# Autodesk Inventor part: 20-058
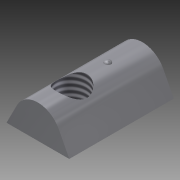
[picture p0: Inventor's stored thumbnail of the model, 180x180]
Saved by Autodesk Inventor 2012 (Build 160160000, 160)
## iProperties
Created: 2004-10
Part Number: 20-058
Material: Steel, High Strength Low Alloy
Document SubType Name: Modeling
Designer: Autodesk, Inc.
Manufacturer: Standard
Standards Organization: Custom
Description: NUT, T SLOT, STANDARD, 40 SERIES, M8
Catalog Web Link: http://www.parker.com/ead/cm1.asp?cmid=809
Vendor: PARKER IPS
Mass: 10.738 g
Surface Area: 10.2004 cm^2
Volume: 1.36964 cm^3
Density: 7.84 g/cm^3
CAGE: 1LJX3
Dept. ID: Product Design
Description #2: ---
Finish #1: ---
Finish #2: ---
Material ID: ---
Project Number: ---
Author: Autodesk, Inc.
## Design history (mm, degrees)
sketch "Sketch2"
  geometry: L1 (6.9, -11.5)-(-6.9, -11.5); L2 (-6.9, -11.5)-(-6.9, 11.5); L3 (-6.9, 11.5)-(6.9, 11.5); L4 (6.9, 11.5)-(6.9, -11.5); 5 further points
  constraints: 8 end point, 3 midpoint, 2 parallel, 2 vertical alignment, 1 horizontal, 1 horizontal alignment, 1 perpendicular
  dimensions: "CenterHole" = 7.5 distance from line of point (0, 4) L3; "Length" = 23 distance of L3.end L1.start; "Width" = 13.8 distance of L2.end L3.end
extrude "NutBase" new body sketch "Sketch2" taper "d4" = 0 deg; distance "Depth" = 7.3
hole "Hole1" sketch "Sketch2" diameter "HoleDia" = 6.647; stored, may be unused: countersink angle "d9" = 90 deg, drill point angle "d11" = 118 deg; dims "d6" = 6, "d7" = 4, "d8" = 2, "d10" = 8
node "MidPlane"
workplane "Work Plane4"
sketch "Sketch3"
  geometry: L1 (0, -7.3)-(13.8, -7.3) reference; L2 (13.8, 0)-(0, 0) reference; L3 (0, 0)-(2.3, -4.488); L4 (11.5, -4.488)-(13.8, 0); L5 (6.9, -2.131)-(6.9, 0); A1 r 5.169 centre (6.9, -2.131) between (2.3, -4.488) and (11.5, -4.488)
  constraints: 6 end point, 3 tangent, 2 point on circle, 1 centre point, 1 midpoint, 1 vertical
  dimensions: "d12" = 9.2 distance of L4.start L3.end (= 0.666667 x Width)
extrude "Standard TSlot" sketch "Sketch3" stored distance "d13" = 10; taper "d14" = 0 deg
sketch "Sketch5"
  geometry: L1 (0, -7.3)-(13.8, -7.3) reference; L2 (13.8, 0)-(0, 0) reference; L3 (0, 0)-(0, -7.3) reference; L4 (6.9, 0)-(6.9, -7.3); L5 (0, -0.8)-(2.95, -0.8); L6 (2.95, -0.8)-(2.95, 0); L7 (2.95, 0)-(0, 0); L8 (0, 0)-(0, -0.8); L9 (13.8, -0.8)-(10.85, -0.8); L10 (10.85, -0.8)-(10.85, 0); L11 (10.85, 0)-(13.8, 0); L12 (13.8, 0)-(13.8, -0.8); 1 further point
  constraints: 18 end point, 5 symmetric about line, 2 midpoint, 2 parallel, 2 point on line, 1 horizontal, 1 perpendicular
  dimensions: "Slot_Width" = 7.9 diameter of L6 L4; "d18" = 0.8 distance between parallel lines of L2 L5
extrude "Self-Align TSlot" cut sketch "Sketch5" stored distance "d19" = 10; taper "d20" = 0 deg
sketch "Sketch6"
  geometry: L1 (0, -7.3)-(13.8, -7.3) reference; L2 (13.8, 0)-(13.8, -7.3) reference; L3 (13.8, 0)-(0, 0) reference; L4 (0, 0)-(0, -7.3) reference; L5 (6.9, 0)-(6.9, -7.3); L6 (0, 0)-(2.95, 0); L7 (2.95, 0)-(2.95, -3.5); L8 (2.95, -3.5)-(0, -3.5); L9 (0, -3.5)-(0, 0); L10 (13.8, 0)-(10.85, 0); L11 (10.85, 0)-(10.85, -3.5); L12 (10.85, -3.5)-(13.8, -3.5); L13 (13.8, -3.5)-(13.8, 0); A1 r 2.5 centre (2.5, -4.8) between (0, -4.8) and (2.5, -7.3); A2 r 2.5 centre (11.3, -4.8) between (11.3, -7.3) and (13.8, -4.8)
  constraints: 18 end point, 4 point on circle, 4 point on line, 4 tangent, 3 symmetric about line, 2 centre point, 2 midpoint, 2 parallel, 1 horizontal, 1 perpendicular, 1 other
  dimensions: "HD_Slot_Depth" = 3.5 distance of L8.end L3.end; "HD_Slot_Width" = 7.9 diameter of L7 L5 (= Slot_Width); "d23" = 2.5 radius of A1
extrude "Heavy Duty TSlot" cut sketch "Sketch6" stored distance "d24" = 10; taper "d25" = 0 deg
sketch "Sketch7"
  geometry: L1 (-6.9, 11.5)-(6.9, 11.5) reference; L2 (-6.9, -11.5)-(-6.9, 11.5) reference; L3 (6.9, -11.5)-(-6.9, -11.5) reference; L4 (6.9, 11.5)-(6.9, -11.5) reference; L5 (-9.66, 0)-(9.66, 0) reference; A1 r 10 centre (0, 1.5) between (6.9, 8.738) and (-6.9, 8.738); A2 r 10 centre (0, -1.5) between (-6.9, -8.738) and (6.9, -8.738); 2 further points
  constraints: 6 point on circle, 4 point on line, 2 centre point, 2 horizontal alignment, 2 midpoint, 2 tangent, 1 other
  dimensions: "Economy_Fillet_Size" = 10 radius of A1
extrude "Economy TSlot" cut sketch "Sketch7" stored distance "d27" = 10; taper "d28" = 0 deg
sketch "Sketch9"
  geometry: C1 r 3.324 at (0, 4) reference; C2 r 4.574 at (0, 4); A1 r 10 centre (0, 2.5) between (8, 8.5) and (-8, 8.5) reference; A2 r 10 centre (0, -2.5) between (-8, -8.5) and (8, -8.5) reference; 2 other entities
  constraints: 2 vertical alignment, 1 centre point, 1 coincident
  dimensions: "d35" = 1.25 radial gap between concentric circles of C1 C2
extrude "Economy TSlot2" cut sketch "Sketch9" distance "d36" = 1.5; taper "d37" = 0 deg
sketch "Sketch4"
  geometry: L1 (6.928, -6.301)-(6.872, -6.301); L2 (6.9, -9.36)-(6.9, 1.56) reference; L3 (13.8, -7.3)-(0, -7.3) reference; L4 (6.9, -6.301)-(6.9, -7.8); L5 (0, 0)-(13.8, 0) reference; A1 r 0.75 centre (6.9, -7.05) between (6.928, -6.301) and (6.872, -6.301)
  constraints: 4 end point, 3 point on circle, 3 point on line, 1 centre point, 1 midpoint
  dimensions: "d15" = 1.5 diameter of A1; "d38" = 7.05 distance from line of L5 A1.centre (computed from Depth)
revolve "SpringBall" sketch "Sketch4" stored, may be unused: angle "d16" = 180 deg
mirror "Double Mirror"
sketch "Sketch10"
  geometry: L1 (6.9, -8.76)-(6.9, 1.46) reference; L2 (0, 0)-(4.036, 0); L3 (4.036, 0)-(4.036, -1.925); L4 (4.036, -1.925)-(0, -1.925); L5 (0, -1.925)-(0, 0); L6 (13.8, 0)-(9.764, 0); L7 (9.764, 0)-(9.764, -1.925); L8 (9.764, -1.925)-(13.8, -1.925); L9 (13.8, -1.925)-(13.8, 0)
  constraints: 16 end point, 3 symmetric about line, 2 parallel, 1 horizontal, 1 perpendicular
  dimensions: "d40" = 5.72756 distance between parallel lines of L7 L3 (= 0.707107 x Zn_C); "d41" = 1.925 distance between parallel lines of L2 L4 (= 0.25 x Zn_E)
extrude "Zn TSlot 1" cut sketch "Sketch10" stored distance "d42" = 1.5; taper "d43" = 0 deg
sketch "Sketch11"
  geometry: L1 (-6.9, -11.5)-(-6.9, 11.5) reference; L2 (6.9, -11.5)-(-6.9, -11.5) reference; L3 (6.9, -11.5)-(-6.9, 2.3); L4 (0, 4)-(-6.9, 10.9); L5 (6.9, 11.5)-(6.9, -11.5) reference; L6 (-6.9, 11.5)-(6.9, -2.3); L7 (-6.9, 11.5)-(6.9, 11.5) reference; C1 r 3.324 at (0, 4) reference; 2 further points
  constraints: 6 end point, 3 point on line, 2 coincident, 2 parallel
  dimensions: "d44" = 45 deg angle of L2 L3; "d45" = 12.16224 diameter of L3 L4 (derived); "d48" = 45 deg angle of L7 L6 (derived)
extrude "Zn TSlot 2" cut sketch "Sketch11" stored distance "d46" = 1.5; taper "d47" = 0 deg
body "Solid1"
other parameters: "SpringBallPos" = -7.66667 (= -0.333333 x Length), "Zn_B" = 27 [user parameter], "Zn_C" = 8.1 [user parameter; used in 1 equation term], "Zn_D" = 7.9 [user parameter], "Zn_E" = 7.7 [user parameter; used in 1 equation term]
